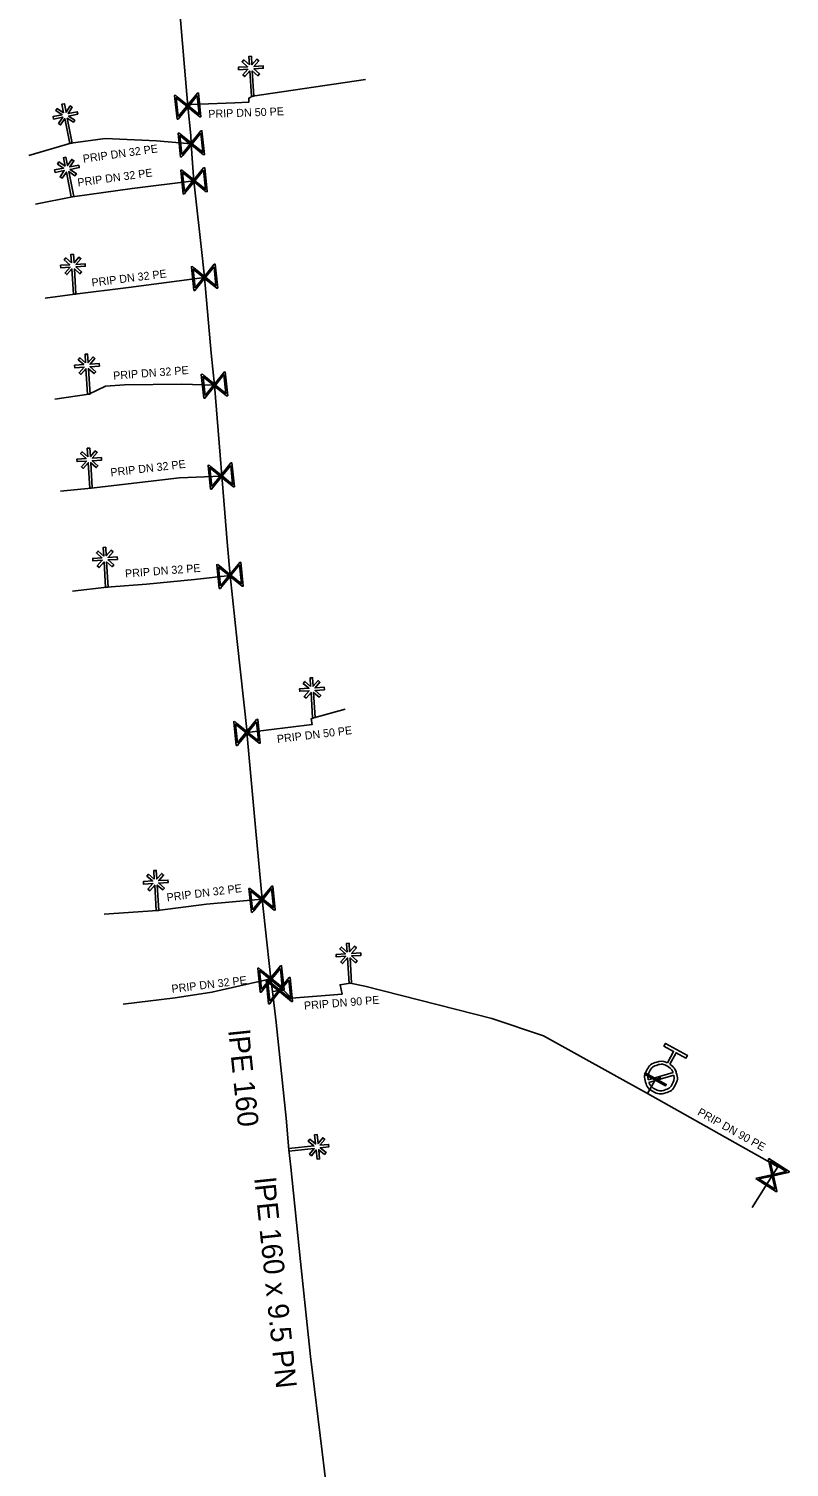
# Model space of a CAD drawing. Extents: x -643842 to -636370, y -1119190 to -1110210.
# Drawn here: x -640837.6 to -640790.1, y -1114607.2 to -1114517.4 of the extents above; entities that cross this region are included whole.
import ezdxf

# ---------------------------------------------------------------- set-up
doc = ezdxf.new("R2010")
doc.units = 0
for name, color, linetype in [('2', 7, 'Continuous'), ('22', 7, 'Continuous'), ('Default', 7, 'Continuous'), ('Level 16', 7, 'Continuous'), ('Level 20', 7, 'Continuous'), ('Level 21', 7, 'Continuous'), ('Level 23', 7, 'Continuous'), ('Level 33', 7, 'Continuous')]:
    doc.layers.add(name, color=color, linetype=linetype)

msp = doc.modelspace()

# ---------------------------------------------------------------- linework, layer by layer
at = {"layer": '2'}
for points in [[(-640823.797, -1114519.618), (-640823.83, -1114519.079), (-640823.674, -1114519.07), (-640823.641, -1114519.603), (-640823.332, -1114519.252), (-640823.215, -1114519.356), (-640823.522, -1114519.705), (-640822.947, -1114519.669), (-640822.938, -1114519.825), (-640823.522, -1114519.861), (-640823.167, -1114520.175), (-640823.27, -1114520.291), (-640823.618, -1114519.985), (-640823.52, -1114521.565), (-640823.676, -1114521.575), (-640823.774, -1114519.99), (-640824.086, -1114520.344), (-640824.202, -1114520.24), (-640823.889, -1114519.884), (-640824.473, -1114519.92), (-640824.482, -1114519.764), (-640823.909, -1114519.729), (-640824.255, -1114519.421), (-640824.153, -1114519.305), (-640823.797, -1114519.618)], [(-640835.4, -1114522.603), (-640835.506, -1114522.074), (-640835.353, -1114522.043), (-640835.247, -1114522.567), (-640834.988, -1114522.177), (-640834.859, -1114522.264), (-640835.116, -1114522.652), (-640834.551, -1114522.538), (-640834.52, -1114522.692), (-640835.095, -1114522.807), (-640834.7, -1114523.069), (-640834.786, -1114523.198), (-640835.172, -1114522.942), (-640834.861, -1114524.494), (-640835.014, -1114524.525), (-640835.326, -1114522.968), (-640835.587, -1114523.361), (-640835.717, -1114523.274), (-640835.455, -1114522.879), (-640836.028, -1114522.994), (-640836.059, -1114522.841), (-640835.495, -1114522.728), (-640835.881, -1114522.47), (-640835.795, -1114522.341), (-640835.4, -1114522.603)], [(-640835.302, -1114525.941), (-640835.406, -1114525.411), (-640835.252, -1114525.381), (-640835.149, -1114525.906), (-640834.889, -1114525.516), (-640834.759, -1114525.604), (-640835.018, -1114525.991), (-640834.453, -1114525.88), (-640834.423, -1114526.033), (-640834.998, -1114526.146), (-640834.604, -1114526.41), (-640834.691, -1114526.539), (-640835.076, -1114526.281), (-640834.771, -1114527.834), (-640834.924, -1114527.865), (-640835.23, -1114526.306), (-640835.493, -1114526.699), (-640835.622, -1114526.611), (-640835.358, -1114526.217), (-640835.932, -1114526.329), (-640835.962, -1114526.176), (-640835.398, -1114526.065), (-640835.782, -1114525.806), (-640835.696, -1114525.677), (-640835.302, -1114525.941)], [(-640834.907, -1114531.988), (-640834.94, -1114531.449), (-640834.784, -1114531.44), (-640834.751, -1114531.973), (-640834.442, -1114531.622), (-640834.325, -1114531.726), (-640834.632, -1114532.075), (-640834.057, -1114532.039), (-640834.048, -1114532.195), (-640834.632, -1114532.231), (-640834.277, -1114532.545), (-640834.38, -1114532.661), (-640834.728, -1114532.355), (-640834.63, -1114533.935), (-640834.786, -1114533.945), (-640834.884, -1114532.36), (-640835.196, -1114532.714), (-640835.312, -1114532.61), (-640834.999, -1114532.254), (-640835.583, -1114532.29), (-640835.592, -1114532.134), (-640835.019, -1114532.099), (-640835.365, -1114531.791), (-640835.263, -1114531.675), (-640834.907, -1114531.988)], [(-640834.027, -1114538.228), (-640834.06, -1114537.689), (-640833.904, -1114537.68), (-640833.871, -1114538.213), (-640833.562, -1114537.862), (-640833.445, -1114537.966), (-640833.752, -1114538.315), (-640833.177, -1114538.279), (-640833.168, -1114538.435), (-640833.752, -1114538.471), (-640833.397, -1114538.785), (-640833.5, -1114538.901), (-640833.848, -1114538.595), (-640833.75, -1114540.175), (-640833.906, -1114540.185), (-640834.004, -1114538.6), (-640834.316, -1114538.954), (-640834.432, -1114538.85), (-640834.119, -1114538.494), (-640834.703, -1114538.53), (-640834.712, -1114538.374), (-640834.139, -1114538.339), (-640834.485, -1114538.031), (-640834.383, -1114537.915), (-640834.027, -1114538.228)], [(-640833.887, -1114544.098), (-640833.92, -1114543.559), (-640833.764, -1114543.55), (-640833.731, -1114544.083), (-640833.422, -1114543.732), (-640833.305, -1114543.836), (-640833.612, -1114544.185), (-640833.037, -1114544.149), (-640833.028, -1114544.305), (-640833.612, -1114544.341), (-640833.257, -1114544.655), (-640833.36, -1114544.771), (-640833.708, -1114544.465), (-640833.61, -1114546.045), (-640833.766, -1114546.055), (-640833.864, -1114544.47), (-640834.176, -1114544.824), (-640834.292, -1114544.72), (-640833.979, -1114544.364), (-640834.563, -1114544.4), (-640834.572, -1114544.244), (-640833.999, -1114544.209), (-640834.345, -1114543.901), (-640834.243, -1114543.785), (-640833.887, -1114544.098)], [(-640832.897, -1114550.298), (-640832.93, -1114549.759), (-640832.774, -1114549.75), (-640832.741, -1114550.283), (-640832.432, -1114549.932), (-640832.315, -1114550.036), (-640832.622, -1114550.385), (-640832.047, -1114550.349), (-640832.038, -1114550.505), (-640832.622, -1114550.541), (-640832.267, -1114550.855), (-640832.37, -1114550.971), (-640832.718, -1114550.665), (-640832.62, -1114552.245), (-640832.776, -1114552.255), (-640832.874, -1114550.67), (-640833.186, -1114551.024), (-640833.302, -1114550.92), (-640832.989, -1114550.564), (-640833.573, -1114550.6), (-640833.582, -1114550.444), (-640833.009, -1114550.409), (-640833.355, -1114550.101), (-640833.253, -1114549.985), (-640832.897, -1114550.298)], [(-640819.977, -1114558.448), (-640820.01, -1114557.909), (-640819.854, -1114557.9), (-640819.821, -1114558.433), (-640819.512, -1114558.082), (-640819.395, -1114558.186), (-640819.702, -1114558.535), (-640819.127, -1114558.499), (-640819.118, -1114558.655), (-640819.702, -1114558.691), (-640819.347, -1114559.005), (-640819.45, -1114559.121), (-640819.798, -1114558.815), (-640819.7, -1114560.395), (-640819.856, -1114560.405), (-640819.954, -1114558.82), (-640820.266, -1114559.174), (-640820.382, -1114559.07), (-640820.069, -1114558.714), (-640820.653, -1114558.75), (-640820.662, -1114558.594), (-640820.089, -1114558.559), (-640820.435, -1114558.251), (-640820.333, -1114558.135), (-640819.977, -1114558.448)], [(-640829.737, -1114570.488), (-640829.77, -1114569.949), (-640829.614, -1114569.94), (-640829.581, -1114570.473), (-640829.272, -1114570.122), (-640829.155, -1114570.226), (-640829.462, -1114570.575), (-640828.887, -1114570.539), (-640828.878, -1114570.695), (-640829.462, -1114570.731), (-640829.107, -1114571.045), (-640829.21, -1114571.161), (-640829.558, -1114570.855), (-640829.46, -1114572.435), (-640829.616, -1114572.445), (-640829.714, -1114570.86), (-640830.026, -1114571.214), (-640830.142, -1114571.11), (-640829.829, -1114570.754), (-640830.413, -1114570.79), (-640830.422, -1114570.634), (-640829.849, -1114570.599), (-640830.195, -1114570.291), (-640830.093, -1114570.175), (-640829.737, -1114570.488)], [(-640817.697, -1114575.038), (-640817.73, -1114574.499), (-640817.574, -1114574.49), (-640817.541, -1114575.023), (-640817.232, -1114574.672), (-640817.115, -1114574.776), (-640817.422, -1114575.125), (-640816.847, -1114575.089), (-640816.838, -1114575.245), (-640817.422, -1114575.281), (-640817.067, -1114575.595), (-640817.17, -1114575.711), (-640817.518, -1114575.405), (-640817.42, -1114576.985), (-640817.576, -1114576.995), (-640817.674, -1114575.41), (-640817.986, -1114575.764), (-640818.102, -1114575.66), (-640817.789, -1114575.304), (-640818.373, -1114575.34), (-640818.382, -1114575.184), (-640817.809, -1114575.149), (-640818.155, -1114574.841), (-640818.053, -1114574.725), (-640817.697, -1114575.038)], [(-640819.398, -1114587.112), (-640818.861, -1114587.056), (-640818.845, -1114587.211), (-640819.377, -1114587.267), (-640819.012, -1114587.561), (-640819.112, -1114587.682), (-640819.473, -1114587.39), (-640819.414, -1114587.963), (-640819.569, -1114587.979), (-640819.63, -1114587.396), (-640819.928, -1114587.765), (-640820.048, -1114587.667), (-640819.757, -1114587.306), (-640821.332, -1114587.47), (-640821.348, -1114587.315), (-640819.768, -1114587.15), (-640820.135, -1114586.854), (-640820.036, -1114586.733), (-640819.668, -1114587.031), (-640819.728, -1114586.449), (-640819.573, -1114586.433), (-640819.513, -1114587.005), (-640819.221, -1114586.645), (-640819.1, -1114586.743), (-640819.398, -1114587.112)]]:
    msp.add_lwpolyline(points, dxfattribs=at)
at = {"layer": 'Default'}
for points in [[(-640797.543, -1114582.05), (-640797.241, -1114582.248), (-640797.139, -1114582.6), (-640797.024, -1114582.996), (-640797.224, -1114583.361), (-640797.422, -1114583.725), (-640797.819, -1114583.841), (-640798.216, -1114583.957), (-640798.582, -1114583.757), (-640798.943, -1114583.56), (-640799.06, -1114583.163), (-640799.178, -1114582.766), (-640798.979, -1114582.403), (-640798.78, -1114582.038), (-640798.384, -1114581.92), (-640798.032, -1114581.814), (-640797.704, -1114581.962)], [(-640797.35, -1114582.565), (-640797.455, -1114582.305), (-640797.712, -1114582.165), (-640798.009, -1114582.003), (-640798.331, -1114582.097), (-640798.653, -1114582.192), (-640798.814, -1114582.488), (-640798.955, -1114582.745), (-640798.903, -1114583.021)], [(-640798.851, -1114583.196), (-640798.744, -1114583.452), (-640798.491, -1114583.591), (-640798.196, -1114583.752), (-640797.873, -1114583.658), (-640797.55, -1114583.564), (-640797.388, -1114583.267), (-640797.25, -1114583.013), (-640797.298, -1114582.74)]]:
    msp.add_open_spline(points, degree=3, dxfattribs=at)
at = {"layer": 'Level 16'}
for points in [[(-640828.318, -1114523.014), (-640828.474, -1114521.522), (-640828.408, -1114521.515), (-640828.311, -1114521.599), (-640827.658, -1114522.128), (-640827.047, -1114521.373), (-640826.982, -1114521.366), (-640826.826, -1114522.858), (-640826.892, -1114522.865), (-640827.645, -1114522.251), (-640828.173, -1114522.904), (-640828.253, -1114523.007), (-640828.318, -1114523.014)], [(-640828.241, -1114522.847), (-640827.713, -1114522.196), (-640828.364, -1114521.669), (-640828.241, -1114522.847)], [(-640827.059, -1114521.527), (-640827.59, -1114522.183), (-640826.936, -1114522.712), (-640827.059, -1114521.527)], [(-640828.098, -1114525.374), (-640828.254, -1114523.882), (-640828.188, -1114523.875), (-640828.091, -1114523.959), (-640827.438, -1114524.488), (-640826.827, -1114523.733), (-640826.762, -1114523.726), (-640826.606, -1114525.218), (-640826.672, -1114525.225), (-640827.425, -1114524.611), (-640827.953, -1114525.264), (-640828.033, -1114525.367), (-640828.098, -1114525.374)], [(-640826.839, -1114523.887), (-640827.37, -1114524.543), (-640826.716, -1114525.072), (-640826.839, -1114523.887)], [(-640828.021, -1114525.207), (-640827.493, -1114524.556), (-640828.144, -1114524.029), (-640828.021, -1114525.207)], [(-640827.928, -1114527.684), (-640828.084, -1114526.192), (-640828.018, -1114526.185), (-640827.921, -1114526.269), (-640827.268, -1114526.798), (-640826.657, -1114526.043), (-640826.592, -1114526.036), (-640826.436, -1114527.528), (-640826.502, -1114527.535), (-640827.255, -1114526.921), (-640827.783, -1114527.574), (-640827.863, -1114527.677), (-640827.928, -1114527.684)], [(-640827.851, -1114527.517), (-640827.323, -1114526.866), (-640827.974, -1114526.339), (-640827.851, -1114527.517)], [(-640826.669, -1114526.197), (-640827.2, -1114526.853), (-640826.546, -1114527.382), (-640826.669, -1114526.197)], [(-640827.268, -1114533.714), (-640827.424, -1114532.222), (-640827.358, -1114532.215), (-640827.261, -1114532.299), (-640826.608, -1114532.828), (-640825.997, -1114532.073), (-640825.932, -1114532.066), (-640825.776, -1114533.558), (-640825.842, -1114533.565), (-640826.595, -1114532.951), (-640827.123, -1114533.604), (-640827.203, -1114533.707), (-640827.268, -1114533.714)], [(-640827.191, -1114533.547), (-640826.663, -1114532.896), (-640827.314, -1114532.369), (-640827.191, -1114533.547)], [(-640826.009, -1114532.227), (-640826.54, -1114532.883), (-640825.886, -1114533.412), (-640826.009, -1114532.227)], [(-640826.648, -1114540.444), (-640826.804, -1114538.952), (-640826.738, -1114538.945), (-640826.641, -1114539.029), (-640825.988, -1114539.558), (-640825.377, -1114538.803), (-640825.312, -1114538.796), (-640825.156, -1114540.288), (-640825.222, -1114540.295), (-640825.975, -1114539.681), (-640826.503, -1114540.334), (-640826.583, -1114540.437), (-640826.648, -1114540.444)], [(-640826.571, -1114540.277), (-640826.043, -1114539.626), (-640826.694, -1114539.099), (-640826.571, -1114540.277)], [(-640825.389, -1114538.957), (-640825.92, -1114539.613), (-640825.266, -1114540.142), (-640825.389, -1114538.957)], [(-640826.228, -1114546.124), (-640826.384, -1114544.632), (-640826.318, -1114544.625), (-640826.221, -1114544.709), (-640825.568, -1114545.238), (-640824.957, -1114544.483), (-640824.892, -1114544.476), (-640824.736, -1114545.968), (-640824.802, -1114545.975), (-640825.555, -1114545.361), (-640826.083, -1114546.014), (-640826.163, -1114546.117), (-640826.228, -1114546.124)], [(-640826.151, -1114545.957), (-640825.623, -1114545.306), (-640826.274, -1114544.779), (-640826.151, -1114545.957)], [(-640824.969, -1114544.637), (-640825.5, -1114545.293), (-640824.846, -1114545.822), (-640824.969, -1114544.637)], [(-640825.678, -1114552.334), (-640825.834, -1114550.842), (-640825.768, -1114550.835), (-640825.671, -1114550.919), (-640825.018, -1114551.448), (-640824.407, -1114550.693), (-640824.342, -1114550.686), (-640824.186, -1114552.178), (-640824.252, -1114552.185), (-640825.005, -1114551.571), (-640825.533, -1114552.224), (-640825.613, -1114552.327), (-640825.678, -1114552.334)], [(-640824.419, -1114550.847), (-640824.95, -1114551.503), (-640824.296, -1114552.032), (-640824.419, -1114550.847)], [(-640825.601, -1114552.167), (-640825.073, -1114551.516), (-640825.724, -1114550.989), (-640825.601, -1114552.167)], [(-640824.618, -1114562.144), (-640824.774, -1114560.652), (-640824.708, -1114560.645), (-640824.611, -1114560.729), (-640823.958, -1114561.258), (-640823.347, -1114560.503), (-640823.282, -1114560.496), (-640823.126, -1114561.988), (-640823.192, -1114561.995), (-640823.945, -1114561.381), (-640824.473, -1114562.034), (-640824.553, -1114562.137), (-640824.618, -1114562.144)], [(-640823.359, -1114560.657), (-640823.89, -1114561.313), (-640823.236, -1114561.842), (-640823.359, -1114560.657)], [(-640824.541, -1114561.977), (-640824.013, -1114561.326), (-640824.664, -1114560.799), (-640824.541, -1114561.977)], [(-640823.678, -1114572.564), (-640823.834, -1114571.072), (-640823.768, -1114571.065), (-640823.671, -1114571.149), (-640823.018, -1114571.678), (-640822.407, -1114570.923), (-640822.342, -1114570.916), (-640822.186, -1114572.408), (-640822.252, -1114572.415), (-640823.005, -1114571.801), (-640823.533, -1114572.454), (-640823.613, -1114572.557), (-640823.678, -1114572.564)], [(-640823.601, -1114572.397), (-640823.073, -1114571.746), (-640823.724, -1114571.219), (-640823.601, -1114572.397)], [(-640822.419, -1114571.077), (-640822.95, -1114571.733), (-640822.296, -1114572.262), (-640822.419, -1114571.077)], [(-640823.128, -1114577.544), (-640823.284, -1114576.052), (-640823.218, -1114576.045), (-640823.121, -1114576.129), (-640822.468, -1114576.658), (-640821.857, -1114575.903), (-640821.792, -1114575.896), (-640821.636, -1114577.388), (-640821.702, -1114577.395), (-640822.455, -1114576.781), (-640822.983, -1114577.434), (-640823.063, -1114577.537), (-640823.128, -1114577.544)], [(-640823.051, -1114577.377), (-640822.523, -1114576.726), (-640823.174, -1114576.199), (-640823.051, -1114577.377)], [(-640822.598, -1114578.274), (-640822.754, -1114576.782), (-640822.688, -1114576.775), (-640822.591, -1114576.859), (-640821.938, -1114577.388), (-640821.327, -1114576.633), (-640821.262, -1114576.626), (-640821.106, -1114578.118), (-640821.172, -1114578.125), (-640821.925, -1114577.511), (-640822.453, -1114578.164), (-640822.533, -1114578.267), (-640822.598, -1114578.274)], [(-640821.869, -1114576.057), (-640822.4, -1114576.713), (-640821.746, -1114577.242), (-640821.869, -1114576.057)], [(-640821.339, -1114576.787), (-640821.87, -1114577.443), (-640821.216, -1114577.972), (-640821.339, -1114576.787)], [(-640822.521, -1114578.107), (-640821.993, -1114577.456), (-640822.644, -1114576.929), (-640822.521, -1114578.107)], [(-640799.086, -1114582.59), (-640797.769, -1114583.308), (-640797.814, -1114583.391), (-640799.131, -1114582.672), (-640799.086, -1114582.59)], [(-640791.363, -1114587.946), (-640790.096, -1114588.749), (-640790.131, -1114588.805), (-640790.258, -1114588.829), (-640791.077, -1114589.013), (-640790.864, -1114589.96), (-640790.9, -1114590.016), (-640792.166, -1114589.212), (-640792.131, -1114589.157), (-640791.182, -1114588.947), (-640791.367, -1114588.127), (-640791.398, -1114588.001), (-640791.363, -1114587.946)], [(-640791.28, -1114588.109), (-640791.096, -1114588.927), (-640790.28, -1114588.744), (-640791.28, -1114588.109)], [(-640790.978, -1114589.855), (-640791.163, -1114589.033), (-640791.984, -1114589.217), (-640790.978, -1114589.855)]]:
    msp.add_lwpolyline(points, dxfattribs=at)
at = {"layer": 'Level 21'}
for points in [[(-640821.34, -1114587.39), (-640821.51, -1114585.41), (-640822.13, -1114579.43), (-640822.36, -1114577.51), (-640822.46, -1114576.72), (-640822.819, -1114573.47), (-640823.01, -1114571.74), (-640823.392, -1114567.497), (-640823.932, -1114561.521), (-640823.95, -1114561.32), (-640824.564, -1114555.63), (-640825.01, -1114551.51), (-640825.16, -1114549.66), (-640825.98, -1114539.62), (-640826.19, -1114537.63), (-640826.6, -1114532.89), (-640826.72, -1114531.71), (-640827.26, -1114526.86), (-640827.345, -1114525.746), (-640827.43, -1114524.55), (-640827.46, -1114524.03), (-640827.65, -1114522.19), (-640827.855, -1114519.764), (-640828.36, -1114513.82)], [(-640821.34, -1114587.39), (-640821.22, -1114588.48), (-640820.6, -1114594.38), (-640819.99, -1114600.31), (-640819.266, -1114606.266), (-640818.53, -1114612.31), (-640818.42, -1114613.15), (-640818.37, -1114613.38), (-640818.09, -1114613.86)]]:
    msp.add_lwpolyline(points, dxfattribs=at)
at = {"layer": 'Level 23'}
for points in [[(-640823.6, -1114521.57), (-640816.56, -1114520.527)], [(-640827.65, -1114522.19), (-640827.46, -1114522.09), (-640824.71, -1114521.99), (-640823.83, -1114521.94), (-640823.83, -1114521.69), (-640823.6, -1114521.57)], [(-640837.575, -1114525.283), (-640834.94, -1114524.51)], [(-640834.94, -1114524.51), (-640832.8, -1114524.21), (-640829.6, -1114524.36), (-640827.43, -1114524.55)], [(-640834.85, -1114527.85), (-640831.13, -1114527.34), (-640827.26, -1114526.86)], [(-640837.146, -1114528.32), (-640834.85, -1114527.85)], [(-640834.71, -1114533.94), (-640831.34, -1114533.52), (-640826.6, -1114532.89)], [(-640836.552, -1114534.179), (-640834.71, -1114533.94)], [(-640833.83, -1114540.18), (-640832.78, -1114539.69), (-640831.59, -1114539.6), (-640828.05, -1114539.56), (-640825.98, -1114539.62)], [(-640835.957, -1114540.503), (-640833.83, -1114540.18)], [(-640833.69, -1114546.05), (-640828.16, -1114545.41), (-640825.56, -1114545.3)], [(-640835.59, -1114546.237), (-640833.69, -1114546.05)], [(-640832.7, -1114552.25), (-640830.22, -1114552.06), (-640827.22, -1114551.77), (-640825.01, -1114551.51)], [(-640834.847, -1114552.489), (-640832.7, -1114552.25)], [(-640823.95, -1114561.32), (-640819.89, -1114560.83), (-640819.94, -1114560.46), (-640819.78, -1114560.4)], [(-640819.78, -1114560.4), (-640817.828, -1114559.862)], [(-640829.54, -1114572.44), (-640826.47, -1114572.05), (-640823.01, -1114571.74)], [(-640832.862, -1114572.676), (-640829.54, -1114572.44)], [(-640831.68, -1114578.29), (-640828.43, -1114577.9), (-640826.14, -1114577.55), (-640822.46, -1114576.72)], [(-640822.36, -1114577.51), (-640821.67, -1114577.43), (-640821.17, -1114577.91), (-640818.01, -1114577.66), (-640818.14, -1114577.08), (-640817.5, -1114576.99)], [(-640817.5, -1114576.99), (-640816.599, -1114577.168), (-640808.668, -1114579.194), (-640805.435, -1114580.264), (-640798.934, -1114583.874), (-640790.797, -1114588.454), (-640791.131, -1114588.981), (-640792.409, -1114590.995)], [(-640798.101, -1114582.88), (-640798.45, -1114582.991), (-640798.934, -1114583.874)]]:
    msp.add_lwpolyline(points, dxfattribs=at)
at = {"layer": 'Level 33'}
for points in [[(-640797.704, -1114581.962), (-640797.311, -1114581.242), (-640797.916, -1114580.912), (-640797.828, -1114580.751), (-640796.456, -1114581.499), (-640796.544, -1114581.661), (-640797.149, -1114581.33), (-640797.543, -1114582.05)], [(-640798.903, -1114583.021), (-640797.35, -1114582.565)], [(-640797.298, -1114582.74), (-640798.851, -1114583.196)]]:
    msp.add_lwpolyline(points, dxfattribs=at)

# ---------------------------------------------------------------- texts
at = {"layer": '22'}
for s, rotation, p in [('PRIP DN 50 PE', 2.08257, (-640826.356, -1114522.928)), ('PRIP DN 32 PE', 7.98011, (-640834.162, -1114525.729)), ('PRIP DN 32 PE', 7.8064, (-640834.5, -1114527.216)), ('PRIP DN 32 PE', 7.10409, (-640833.625, -1114533.467)), ('PRIP DN 32 PE', 4.32506, (-640832.287, -1114539.279)), ('PRIP DN 32 PE', 6.60161, (-640832.446, -1114545.325)), ('PRIP DN 32 PE', 4.38104, (-640831.544, -1114551.644)), ('PRIP DN 50 PE', 6.88172, (-640822.049, -1114561.981)), ('PRIP DN 32 PE', 7.23984, (-640828.933, -1114571.88)), ('PRIP DN 32 PE', 6.84277, (-640828.631, -1114577.589)), ('PRIP DN 90 PE', 4.52347, (-640820.371, -1114578.638)), ('PRIP DN 90 PE', 330.77289, (-640795.873, -1114585.188))]:
    msp.add_text(s, height=0.5, rotation=rotation, dxfattribs=at).set_placement(p)
at = {"layer": 'Level 20'}
for s, rotation, p in [('lPE 160', 275.91922, (-640825.124, -1114579.958)), ('lPE 160 x 9.5 PN ', 275.9989, (-640823.501, -1114589.191))]:
    msp.add_text(s, height=1.3, rotation=rotation, dxfattribs=at).set_placement(p)

doc.saveas('drawing.dxf')
